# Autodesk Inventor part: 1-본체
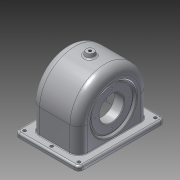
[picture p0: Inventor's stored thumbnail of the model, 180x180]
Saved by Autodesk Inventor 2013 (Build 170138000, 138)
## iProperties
Created: 2015-09
Part Number: 1-본체
Material: 알루미늄 6061
Document SubType Name: Modeling
Designer: Administrator
Density: 2.40731 g/cm^3
Mass: 609.629 g
Surface Area: 905.095 cm^2
Volume: 253.241 cm^3
Author: Administrator
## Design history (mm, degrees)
sketch "스케치1"
  geometry: L1 (-52, 70)-(52, 70); L2 (52, 70)-(52, -70); L3 (52, -70)-(-52, -70); L4 (-52, -70)-(-52, 70); 3 further points
  constraints: 8 end point, 2 midpoint, 2 parallel, 1 horizontal, 1 horizontal alignment, 1 perpendicular, 1 vertical alignment
  dimensions: "d0" = 104 distance between parallel lines of L2 L4; "d2" = 140 distance between parallel lines of L3 L1
extrude "돌출1" new body sketch "스케치1" distance "d3" = 7; taper "d4" = 0 deg
node "작업 평면3"
sketch "스케치4"
  geometry: L1 (70, 7)-(-70, 7) reference; L2 (-57, 7)-(57, 7); L3 (57, 7)-(57, 104); L4 (57, 104)-(-57, 104); L5 (-57, 104)-(-57, 7); 2 further points
  constraints: 8 end point, 2 parallel, 1 horizontal, 1 midpoint, 1 perpendicular, 1 point on line, 1 vertical alignment
  dimensions: "d11" = 97 distance between parallel lines of L4 L2; "d13" = 114 distance between parallel lines of L3 L5
extrude "돌출2" join sketch "스케치4" stored distance "d14" = 77; taper "d15" = 0 deg
feature "쉘1" dims "d16" = 5, "d17" = 7
fillet "모깎기1" dims "d18" = 57
fillet "모깎기2" dims "d19" = 51
node "작업 평면5"
sketch "스케치6"
  geometry: C1 r 6 at (0, 0); 1 further point
  constraints: 1 centre point, 1 coincident
  dimensions: "d22" = 12 diameter of C1
extrude "돌출3" join sketch "스케치6" stored distance "d24" = 77; taper "d25" = 0 deg
sketch "스케치7"
  geometry: 3 further points
  constraints: 1 coincident
hole "구멍1" sketch "스케치7" at (0, 0) diameter "d27" = 4.459; stored, may be unused: countersink angle "d31" = 90 deg, drill point angle "d33" = 0 deg; dims "d28" = 6, "d29" = 4, "d30" = 2, "d32" = 8
sketch "스케치10"
  geometry: C1 r 31 at (47, 0); A1 r 57 centre (47, 0) between (47, -57) and (47, 57) reference; 1 further point
  constraints: 1 centre point, 1 coincident
  dimensions: "d36" = 62 diameter of C1
extrude "돌출4" join sketch "스케치10" distance "d39" = 10; taper "d40" = 0 deg
sketch "스케치11"
  geometry: C1 r 31 at (0, 0) reference; C2 r 20 at (0, 0); 1 further point
  constraints: 1 centre point, 1 coincident
  dimensions: "d41" = 40 diameter of C2
extrude "돌출5" cut sketch "스케치11" stored distance "d43" = 0; taper "d44" = 0 deg
sketch "스케치12"
  geometry: C1 r 20 at (0, 0) reference; 2 further points
  constraints: 1 horizontal alignment
  dimensions: "d45" = 24 distance of point (24, 0) C1.centre
hole "구멍2" sketch "스케치12" at (24, 0) diameter "d46" = 2.459; stored, may be unused: countersink angle "d50" = 90 deg, drill point angle "d52" = 118 deg; dims "d47" = 6, "d48" = 4, "d49" = 2, "d51" = 8
sketch "스케치14"
  geometry: C1 r 35 at (-47, 0); A1 r 57 centre (-47, 0) between (-47, 57) and (-47, -57) reference; 1 further point
  constraints: 1 centre point, 1 coincident
  dimensions: "d56" = 70 diameter of C1
extrude "돌출6" cut sketch "스케치14" distance "d58" = 4; taper "d59" = 0 deg
feature "면 기울기3" dims angle "d151" = 15 deg
feature "면 기울기2" dims angle "d60" = 35 deg
sketch "스케치16"
  geometry: C1 r 35 at (0, 0) reference; C2 r 33 at (0, 0); 1 further point
  constraints: 1 centre point, 1 coincident
  dimensions: "d63" = 66 diameter of C2
extrude "돌출7" join sketch "스케치16" distance "d65" = 1; taper "d66" = 0 deg
chamfer "모따기1" distance "d71" = 1; stored, may be unused: second distance "d72" = 2, angle "d73" = 45 deg
node "작업 평면6"
sketch "스케치8"
  geometry: L1 (-38.5, 47)-(-38.5, 104) reference; L2 (-38.5, 47)-(-38.5, 7) reference; L3 (-33.5, 48)-(-33.5, 0) reference; L4 (-33.5, 48)-(-33.5, 99) reference; L5 (33.5, 99)-(33.5, 48) reference; L6 (33.5, 0)-(33.5, 48) reference; L7 (38.5, 7)-(38.5, 47) reference; L8 (38.5, 104)-(38.5, 47) reference; L9 (33.5, 48)-(19.5, 48); L10 (19.5, 48)-(19.5, 76); L11 (19.5, 76)-(33.5, 87.747); 1 further point
  constraints: 6 end point, 2 perpendicular, 1 point on line
  dimensions: "d82" = 56 diameter of L10.end L9; "d84" = 14 distance between parallel lines of L5 L10; "d86" = 50 deg angle of L11 L10
revolve "회전1" sketch "스케치8" stored, may be unused: angle "d87" = 90 deg
sketch "스케치19"
  geometry: C1 r 33 at (0, 0) reference; C2 r 20 at (0, 0); 1 further point
  constraints: 1 centre point, 1 coincident
  dimensions: "d88" = 40 diameter of C2
extrude "돌출9" cut sketch "스케치19" stored distance "d90" = 0; taper "d91" = 0 deg
sketch "스케치20"
  geometry: C1 r 20 at (0, 0) reference; 2 further points
  constraints: 1 horizontal alignment
  dimensions: "d92" = 28 distance of C1.centre point (-28, 0)
hole "구멍4" sketch "스케치20" at (-28, 0) diameter "d93" = 2.459; stored, may be unused: countersink angle "d97" = 90 deg, drill point angle "d99" = 118 deg; dims "d94" = 7, "d95" = 4, "d96" = 2, "d98" = 9
fillet "모깎기3" dims "d103" = 3
fillet "모깎기4" dims "d104" = 14
fillet "모깎기5" dims "d105" = 9
fillet "모깎기6" dims "d106" = 1
fillet "모깎기7" dims "d107" = 7
fillet "모깎기9" dims "d111" = 0.5
chamfer "모따기2" distance "d112" = 1; stored, may be unused: second distance "d113" = 2, angle "d114" = 45 deg
fillet "모깎기10" dims "d115" = 3
sketch "스케치22"
  geometry: L1 (63, 0)-(63, 39) reference; L2 (-20.5, 47)-(69.5, 47) reference; 2 further points
  constraints: 1 other
  dimensions: "d116" = 38.5 distance from line of L1 point (24.5, 17); "d117" = 30 distance from line of L2 point (24.5, 17)
feature "엠보싱1" sketch "스케치22" dims "d118" = 0.5, "d119" = 0
fillet "모깎기11" dims "d120" = 3
sketch "스케치23"
  geometry: C1 r 2.5 at (-44, 62); 1 further point
  constraints: 1 centre point
  dimensions: "d121" = 44 horizontal distance of point (0, 0) C1.centre; "d122" = 62 vertical distance of C1.centre point (0, 0); "d123" = 5 diameter of C1
extrude "돌출10" cut sketch "스케치23" stored distance "d124" = 0; taper "d125" = 0 deg
sketch "스케치25"
  geometry: C1 r 2.5 at (0, 62); 1 further point
  constraints: 1 centre point, 1 vertical alignment
  dimensions: "d138" = 5 diameter of C1; "d140" = 62 distance of C1.centre point (0, 0)
extrude "돌출11" cut sketch "스케치25" stored distance "d141" = 0; taper "d142" = 0 deg
chamfer "모따기3" distance "d146" = 1; stored, may be unused: second distance "d147" = 2, angle "d148" = 45 deg
fillet "모깎기12" dims "d149" = 3
node "솔리드1"
pattern_circular "원형 패턴1" dims angle "d54" = 360 deg
pattern_circular "원형 패턴2" dims angle "d101" = 360 deg
mirror "대칭1"
mirror "대칭2"
pattern_linear "직사각형 패턴3" dims "d145" = 124
other parameters: "d10" = 90 deg, "d34" = 90 deg
